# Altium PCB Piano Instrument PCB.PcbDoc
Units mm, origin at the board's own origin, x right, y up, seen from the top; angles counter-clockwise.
Board outline 53.34 x 96.77 mm, 2 copper layers (Top Layer, Bottom Layer); 9 components, 11 nets, 74 pads, 0 vias.
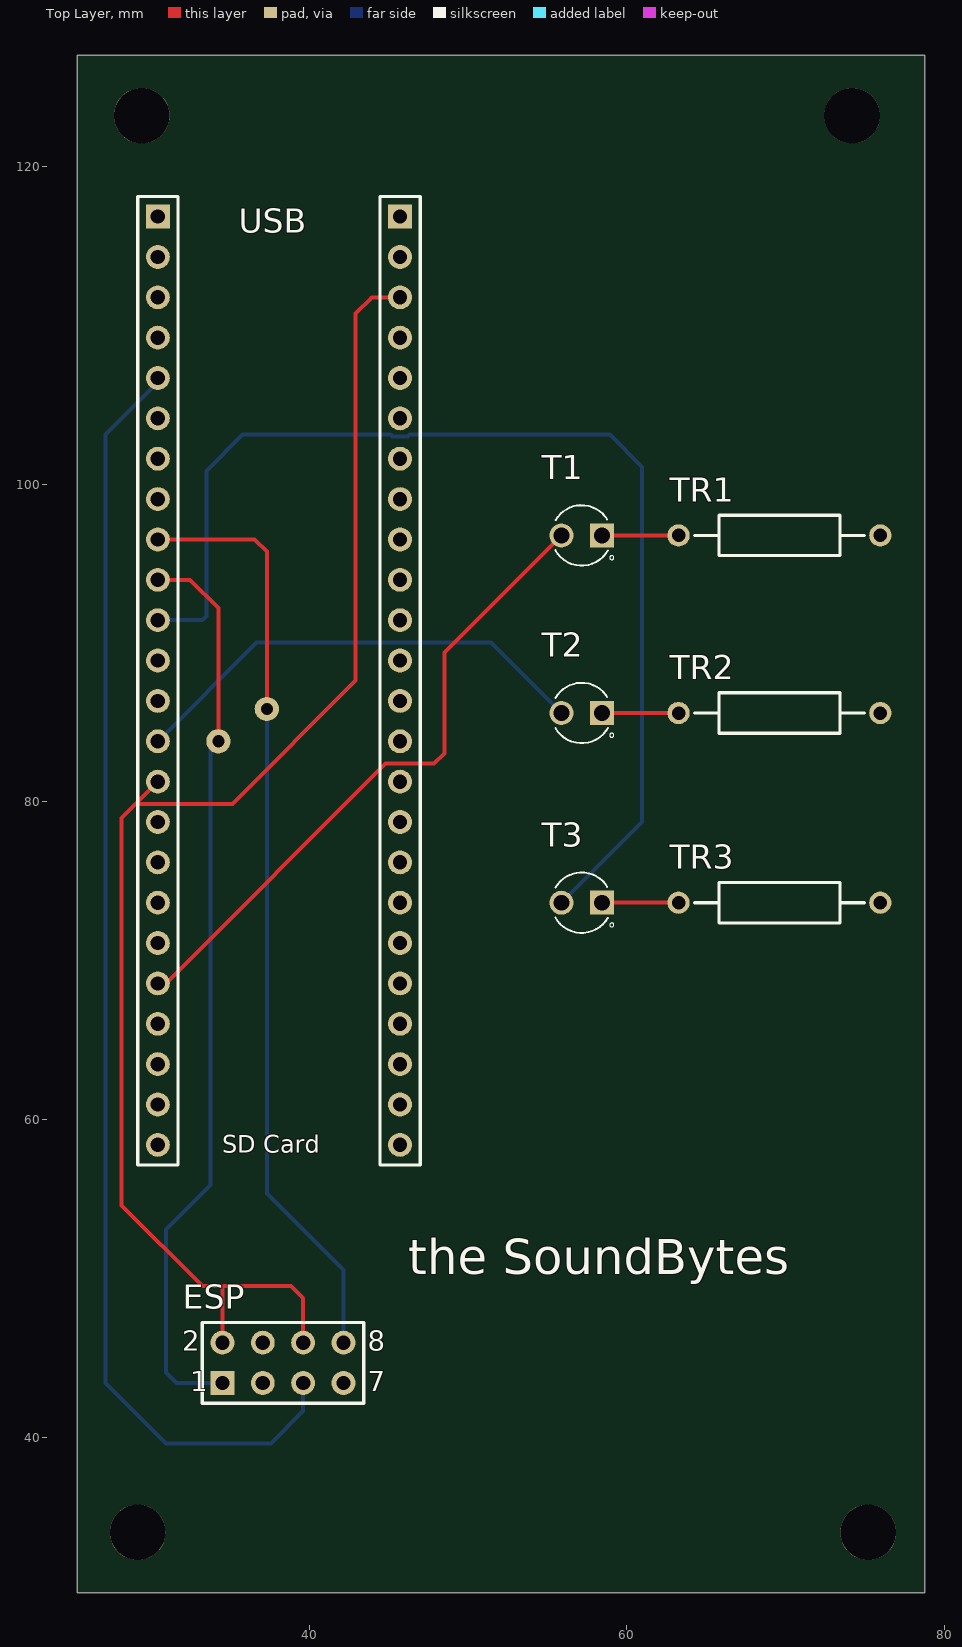
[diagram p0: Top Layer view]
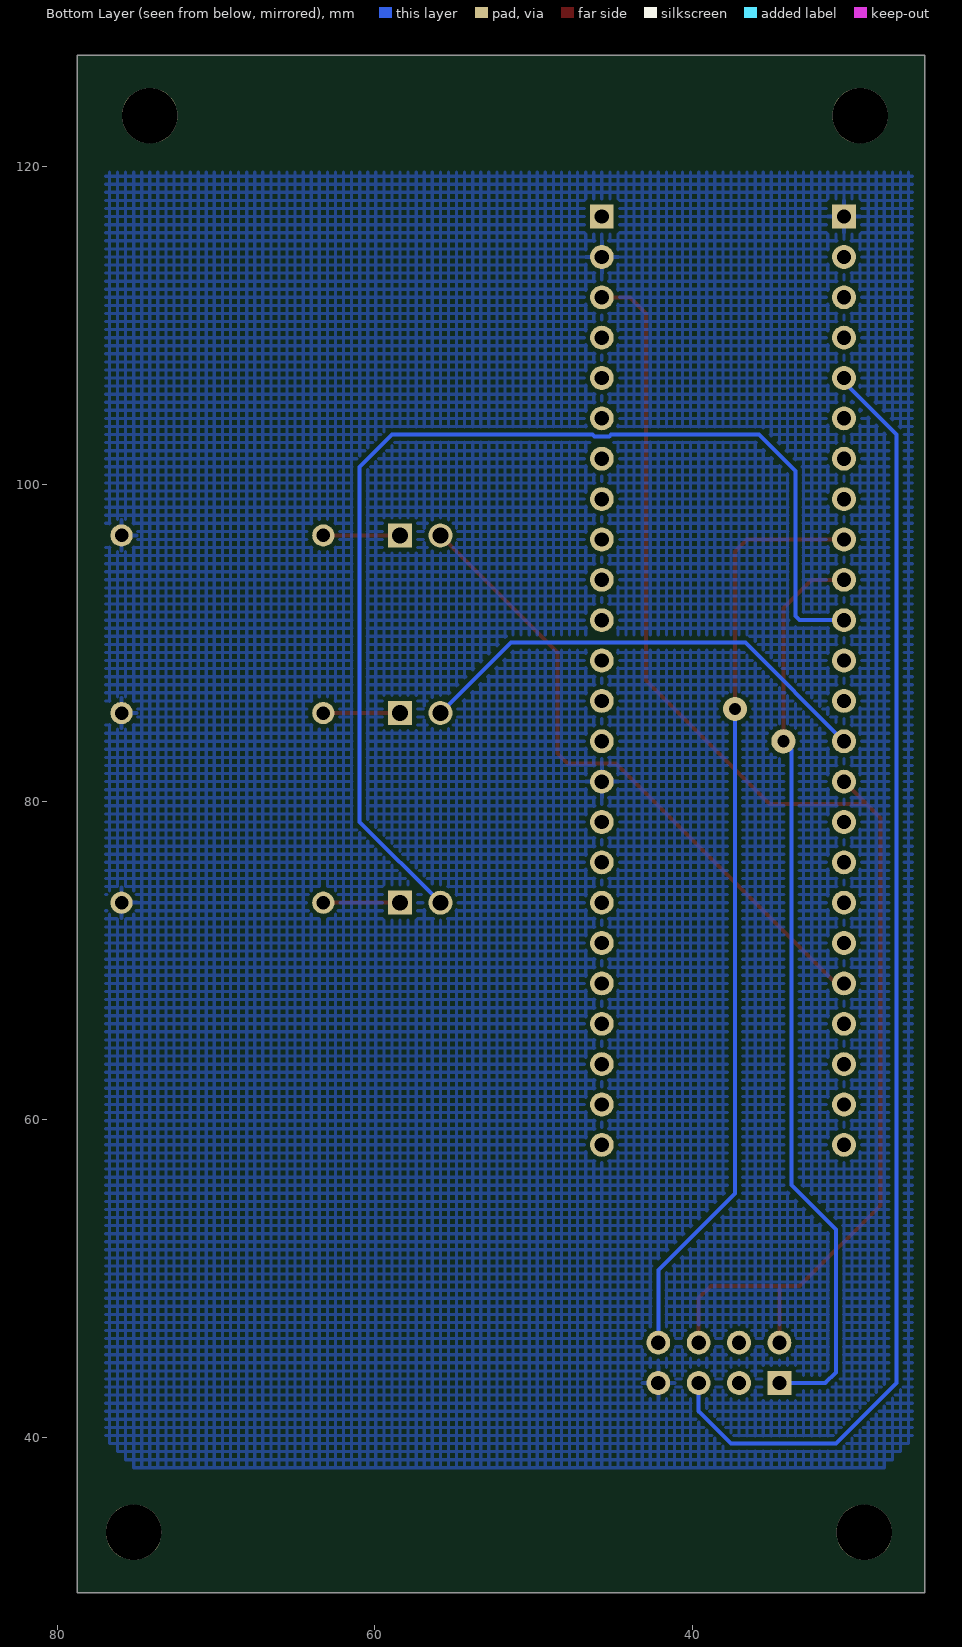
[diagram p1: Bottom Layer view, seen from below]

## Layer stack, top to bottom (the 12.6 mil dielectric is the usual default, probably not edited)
Top Solder: solder mask 0.0102, Solder Resist, Dk 3.5
Top Layer: signal copper 0.0356
Dielectric 1: dielectric 0.32, FR-4, Dk 4.8
Bottom Layer: signal copper 0.0356
Bottom Solder: solder mask 0.0102, Solder Resist, Dk 3.5

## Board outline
25.4,30.226 78.74,30.226 78.74,127 25.4,127

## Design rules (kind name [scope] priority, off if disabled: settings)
Clearance [All] p1: gap=0.254
PolygonConnect [All] p1: connectstyle=Relief reliefconductorwidth=0.254 reliefentries=4 polygonreliefangle="90 Angle" airgapwidth=0.254
RoutingVias [All] p1: holewidth=0.711 width=1.27 viastyle="Through Hole" minholewidth=0.711 minwidth=1.27 maxholewidth=0.711 maxwidth=1.27
SolderMaskExpansion [All] p1: expansion=0.102
Width [All] p1: maxlimit=0.254 minlimit=0.254 preferedwidth=0.254
30 further rules are at their usual default settings.

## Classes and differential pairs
component class "Piano Instrument PCB": ESP T1 T2 T3 TR1 TR2 TR3

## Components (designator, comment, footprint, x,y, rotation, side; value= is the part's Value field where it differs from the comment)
ESP "Header 4X2" HDR2X4 34.544,43.434 r0 top (schematic designator ESP?)
T1 "LTL-1CHYE" LED_LTL-1CHYE_LTL-1CHYE(Primary) 57.15,96.774 r180 top
T2 "LTL-1CHYE" LED_LTL-1CHYE_LTL-1CHYE(Primary) 57.15,85.598 r180 top
T3 "LTL-1CHYE" LED_LTL-1CHYE_LTL-1CHYE(Primary) 57.15,73.66 r180 top
"Teensy L" "Header 24" HDR1X24 30.48,116.84 r270 top
"Teensy R" "Header 24" HDR1X24 45.72,116.84 r270 top
TR1 "" AXIAL-0.5 69.596,96.774 r180 top
TR2 "" AXIAL-0.5 69.596,85.598 r180 top
TR3 "" AXIAL-0.5 69.596,73.66 r180 top

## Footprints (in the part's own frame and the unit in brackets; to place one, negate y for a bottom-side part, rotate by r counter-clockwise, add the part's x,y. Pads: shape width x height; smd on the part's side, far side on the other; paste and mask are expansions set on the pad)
AXIAL-0.5 [mm] "Axial Device, Thru-Hole; 2 Leads; 0.5 in Pin Spacing"
  round 1.4 hole 0.85: 1(-6.35,0) 2(6.35,0)
  silkscreen extent -5.33,-1.27 5.33,1.27
HDR1X24 [mm] "Connector; Header; 24 Position"
  rect 1.5x1.5 hole 0.9: 1(0,0)
  round 1.5 hole 0.9: 2(2.54,0) 3(5.08,0) 4(7.62,0) 5(10.16,0) 6(12.7,0) 7(15.24,0) 8(17.78,0) 9(20.32,0) 10(22.86,0) 11(25.4,0) 12(27.94,0) 13(30.48,0) 14(33.02,0) 15(35.56,0) 16(38.1,0) 17(40.64,0) 18(43.18,0) 19(45.72,0) 20(48.26,0) 21(50.8,0) 22(53.34,0) 23(55.88,0) 24(58.42,0)
  silkscreen extent -1.27,-1.27 59.69,1.27
HDR2X4 [mm] "Connector; Header; 4x2 Position"
  rect 1.5x1.5 hole 0.9: 1(0,0)
  round 1.5 hole 0.9: 2(0,2.54) 3(2.54,0) 4(2.54,2.54) 5(5.08,0) 6(5.08,2.54) 7(7.62,0) 8(7.62,2.54)
  silkscreen extent -1.27,-1.27 8.89,3.81
LED_LTL-1CHYE_LTL-1CHYE(Primary) [mm]
  round 1.508 hole 1: A(1.27,0)
  rect 1.508x1.508 hole 1: C(-1.27,0)
  silkscreen extent -2.03,-1.9 1.66,1.9

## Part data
ESP: "Header, 4-Pin, Dual row"
T1 T2 T3: "Yellow 3.1 mm 45° Tinted Clear 40 mcd 2.1 V LED Through Hole"
"Teensy L" "Teensy R": "Header, 24-Pin"
TR1 TR2 TR3: library part "Res Semi", "Semiconductor Resistor"

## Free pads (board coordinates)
  round 3.5 hole 3.5: 0(29.464,123.19) 1(74.168,123.19) 2(29.21,34.036) 3(75.184,34.036)
  round 1.524 hole 0.762: 4(37.338,85.852) 5(34.29,83.82)

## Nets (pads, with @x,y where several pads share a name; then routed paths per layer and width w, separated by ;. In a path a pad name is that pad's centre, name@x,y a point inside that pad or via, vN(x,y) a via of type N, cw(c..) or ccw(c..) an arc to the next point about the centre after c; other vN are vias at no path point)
3V3: "Teensy L.15" "Teensy R.3" ESP.2 ESP.6 | length 91.2
  Top Layer w0.254: 30.48,81.28 29.071,79.871 ; ESP.2 34.544,49.53 ; ESP.6 39.624,48.768 38.862,49.53 34.544,49.53 ; 45.72,111.76 43.942,111.76 42.926,110.744 42.926,87.63 35.167,79.871 29.071,79.871 ; 29.071,79.871 28.194,78.994 28.194,54.61 33.274,49.53 34.544,49.53
24: "Teensy L.14" T2.A | length 29.8
  Bottom Layer w0.254: 30.48,83.82 36.691,90.031 51.447,90.031 T2.A
28: "Teensy L.20" T1.A | length 40.8
  Top Layer w0.254: 30.48,68.58 30.988,68.58 44.819,82.411 47.867,82.411 48.514,83.058 48.514,89.408 T1.A
GND: "Teensy L.1" "Teensy R.2" "Teensy R.15" ESP.7 TR1.1 TR2.1 TR3.1
NetT1_C: T1.C TR1.2 | length 4.8
  Top Layer w0.254: T1.C TR1.2
NetT2_C: T2.C TR2.2 | length 4.8
  Top Layer w0.254: T2.C TR2.2
NetT3_A: "Teensy L.11" T3.A | length 71.1
  Bottom Layer w0.254: 30.48,91.44 33.274,91.44 33.528,91.694 33.528,100.838 35.814,103.124 45.137,103.124 45.252,103.009 46.188,103.009 46.303,103.124 58.928,103.124 60.96,101.092 60.96,78.74 T3.A
NetT3_C: T3.C TR3.2 | length 4.8
  Top Layer w0.254: T3.C TR3.2
PIN3: "Teensy L.5" ESP.5 | length 81.3
  Bottom Layer w0.254: 30.48,106.68 30.48,106.426 27.178,103.124 27.178,43.434 30.988,39.624 37.592,39.624 39.624,41.656 ESP.5
PIN7: "Teensy L.9" ESP.8 pad.4 | length 59
  Top Layer w0.254: 30.48,96.52 36.576,96.52 37.338,95.758 pad.4
  Bottom Layer w0.254: pad.4 37.338,55.372 42.164,50.546 ESP.8
PIN8: "Teensy L.10" ESP.1 pad.5 | length 57.8
  Top Layer w0.254: 30.48,93.98 32.512,93.98 34.29,92.202 pad.5
  Bottom Layer w0.254: pad.5 33.782,83.312 33.782,55.88 30.988,53.086 30.988,44.105 31.659,43.434 ESP.1
pads on no net: "Teensy L.2" "Teensy L.3" "Teensy L.4" "Teensy L.6" "Teensy L.7" "Teensy L.8" "Teensy L.12" "Teensy L.13" "Teensy L.16" "Teensy L.17" "Teensy L.18" "Teensy L.19" "Teensy L.21" "Teensy L.22" "Teensy L.23" "Teensy L.24" "Teensy R.1" "Teensy R.4" "Teensy R.5" "Teensy R.6" "Teensy R.7" "Teensy R.8" "Teensy R.9" "Teensy R.10" "Teensy R.11" "Teensy R.12" "Teensy R.13" "Teensy R.14" "Teensy R.16" "Teensy R.17" "Teensy R.18" "Teensy R.19" "Teensy R.20" "Teensy R.21" "Teensy R.22" "Teensy R.23" "Teensy R.24" ESP.3 ESP.4

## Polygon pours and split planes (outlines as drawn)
GND on Bottom Layer "GND" (hatched 90Degree grid 0.508 track 0.203, pour order 0): 27.178,119.634 76.962,119.634 76.962,39.878 74.93,37.846 74.676,38.1 28.194,38.1 27.94,38.1 26.416,39.624 26.162,39.878 26.162,119.634 28.702,119.634

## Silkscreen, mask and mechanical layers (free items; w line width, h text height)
Top Overlay:
  text "USB" at 35.56,115.824 h1.52
  text "SD Card" at 34.544,57.912 h1.1
  text "the SoundBytes" at 46.228,50.292 h2.2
